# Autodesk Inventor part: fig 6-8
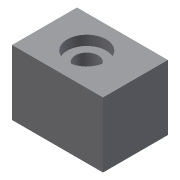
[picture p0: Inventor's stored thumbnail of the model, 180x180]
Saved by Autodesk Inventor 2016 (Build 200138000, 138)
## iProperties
Created: 2009-09
Part Number: fig 6-8
Document SubType Name: Modeling
Designer: Sham
Density: 1 g/cm^3
Material: Generic
Appearance: Default
Author: Sham
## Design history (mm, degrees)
sketch "Sketch1"
  geometry: L1 (-28, 20)-(0, 20); L2 (0, 20)-(0, 0); L3 (0, 0)-(-28, 0); L4 (-28, 0)-(-28, 20)
  constraints: 8 end point, 2 parallel, 1 horizontal, 1 perpendicular
extrude "Extrusion1" new body sketch "Sketch1" distance "d0" = 20; taper "d1" = 0 deg
hole "Hole1" diameter "d4" = 7; stored, may be unused: countersink angle "d8" = 90 deg, drill point angle "d10" = 118 deg; dims "d2" = 10, "d3" = 15, "d5" = 6, "d6" = 12, "d7" = 3, "d9" = 15
body "Solid1"
